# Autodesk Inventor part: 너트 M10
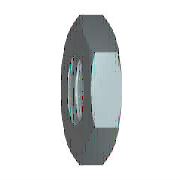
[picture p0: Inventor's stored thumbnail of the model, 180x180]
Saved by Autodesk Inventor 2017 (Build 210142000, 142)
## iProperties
IsCustomPart: 1
Created: 2012-02
Part Number: 너트 M10
Material: 강철, 연강
Description: 6각 가는 너트 - 이중 모따기
Document SubType Name: Modeling
Standard: JIS B 1181
Designer: mduedu
Standards Organization: JIS
Language: ko-KR
Size Designation: A/B M10
Categories: <MemberInstance><Categories><Category DisplayName="조임쇠" InternalName="e4da775c-781d-43d5-af7c-5136215cf5a6" Mnemonic="FSTN"><Category DisplayName="너트" InternalN
Density: 1 g/cm^3
Appearance: 주황색
Author: mduedu
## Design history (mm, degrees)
sketch "스케치1"
  geometry: L1 (-9.238, 0)-(-4.619, 8); L2 (-4.619, 8)-(4.619, 8); L3 (4.619, 8)-(9.238, 0); L4 (9.238, 0)-(4.619, -8); L5 (4.619, -8)-(-4.619, -8); L6 (-4.619, -8)-(-9.238, 0); 2 further points
  constraints: 12 end point, 1 coincident, 1 horizontal, 11 other
  dimensions: "d0" = 18.47521 distance of L3.end L1.start (= 1.1547 x SW)
extrude "본체" new body sketch "스케치1" distance "d1" = 5 (= KOH); taper "d2" = 0 deg
sketch "스케치2"
  geometry: L1 (0, 4.619)-(0, 9.238) reference; L2 (0, 9.238)-(5, 9.238) reference; L3 (5, 4.619)-(5, 9.238) reference; L4 (-1, 0)-(6, 0) reference; L5 (0.715, 9.238)-(0, 8); L6 (4.285, 9.238)-(5, 8)
  constraints: 4 end point, 4 point on line
  dimensions: "d3" = 30 deg angle of L1 L5 (= ANG1); "d4" = 30 deg angle of L3 L6 (= ANG2); "d5" = 16 diameter of L5.end L4 (= SW0); "d6" = 16 diameter of L6.end L4 (= SW01)
revolve "모따기1" sketch "스케치2" stored, may be unused: angle "d7" = 90 deg
sketch "스케치3"
  geometry: A1 r 8 centre (0, 0) between (-4, -6.928) and (4, -6.928) reference; 1 further point
  constraints: 1 coincident
hole "스레드" sketch "스케치3" at (0, 0) diameter "d25" = 8.376; stored, may be unused: countersink angle "d29" = 82 deg, drill point angle "d31" = 118 deg; dims "d26" = 6, "d27" = 4, "d28" = 2, "d30" = 8
workaxis "Work Axis1"
workplane "Work Plane1"
body "Solid1"
chamfer "모따기2" distance "d8" = 0.8119 (= -0.5 x GD1 + 0.5 x NND); stored, may be unused: angle "d9" = 30 deg, second distance "d40" = 0.8119 (= -0.5 x GD1 + 0.5 x NND)
chamfer "모따기3" distance "d10" = 0.8119 (= -0.5 x GD1 + 0.5 x NND); stored, may be unused: angle "d11" = 30 deg, second distance "d41" = 0.8119 (= -0.5 x GD1 + 0.5 x NND)
other parameters: "ANG1" = 30 deg [user parameter; used in 1 equation term], "ANG2" = 30 deg [user parameter; used in 1 equation term], "KOH" = 5 [user parameter; used in 1 equation term], "SW" = 16 [user parameter; used in 4 equation terms], "SW0" = 16 (= SW) [user parameter; used in 1 equation term], "SW01" = 16 (= SW) [user parameter; used in 1 equation term], "GD1" = 8.3762 (computed from THREADDIA, PTC, TOA) [user parameter; used in 4 equation terms], "d13" = 0, "d14" = 0, "d39" = 0, "d42" = 0, "GUL" = 0.8119 (= 0.541266 x PTC) [user parameter], "TPU" = 6.66667 (computed from PTC) [user parameter], "TOA" = 30 deg [user parameter; used in 1 equation term], "PTC" = 1.5 [user parameter; used in 4 equation terms], "E0" = 18.48 (= 1.155 x SW) [user parameter], "GAL" = 0.8119 (= 0.541266 x PTC) [user parameter]
